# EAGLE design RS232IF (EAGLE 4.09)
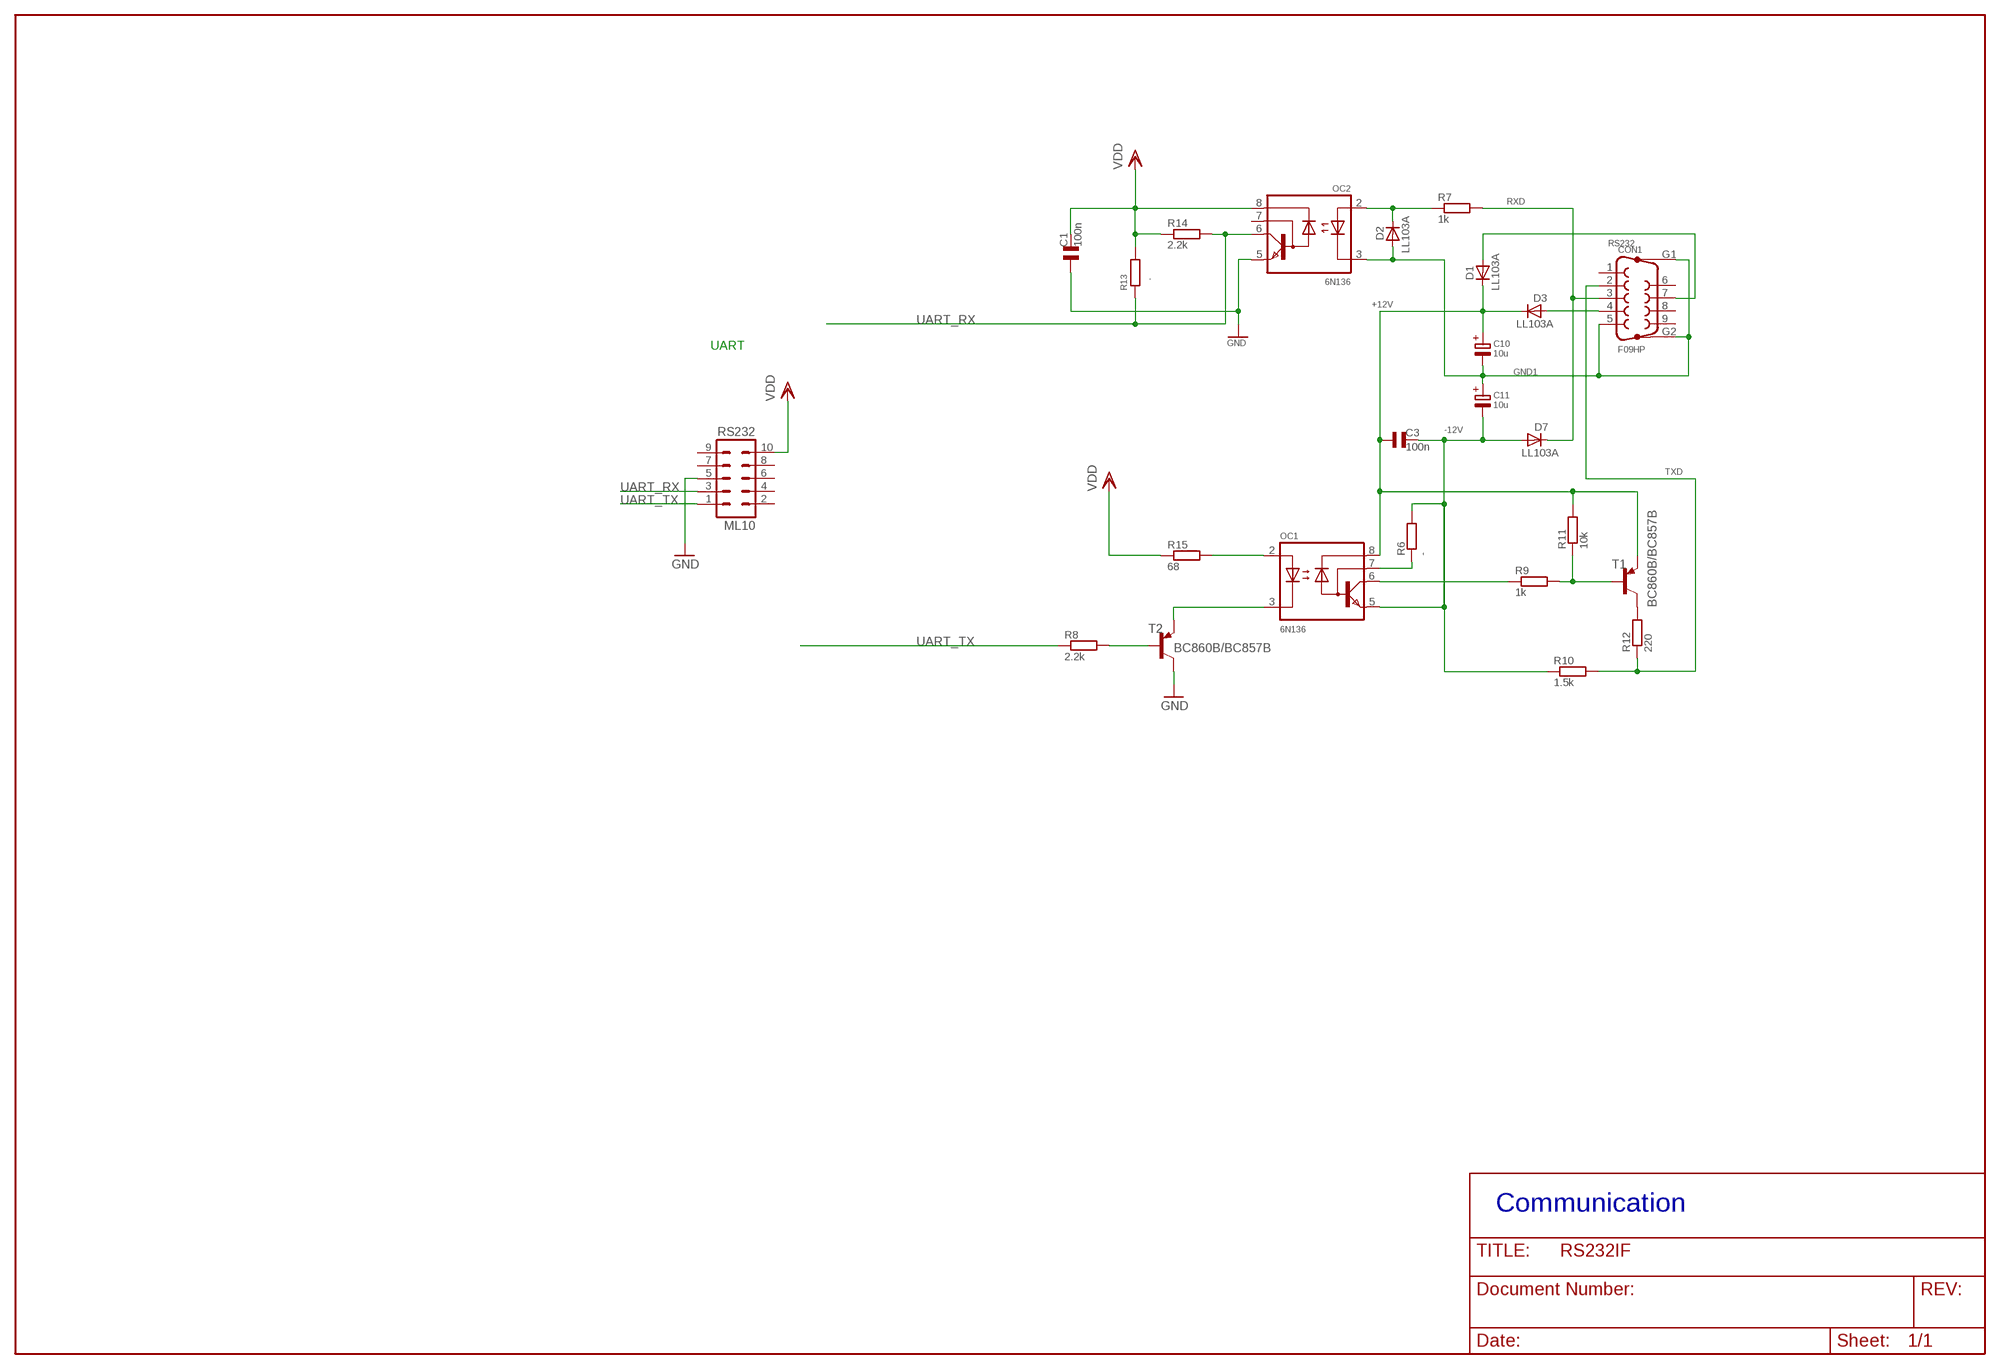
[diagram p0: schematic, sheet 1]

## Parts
C1  100n  CSMD0805  [CSMD0805]
C3  100n  CSMD0805  [CSMD0805]
C10  10u  ELKO  [7243]
C11  10u  ELKO  [7243]
CON1  F09HP  [F09HP]
D1  LL103A  D  [SOD-80]
D2  LL103A  D  [SOD-80]
D3  LL103A  D  [SOD-80]
D7  LL103A  D  [SOD-80]
OC1  6N136  6N135  [DIL08]
OC2  6N136  6N135  [DIL08]
R6  -  R_0805  [0805]
R7  1k  R_0805  [0805]
R8  2.2k  R_0805  [0805]
R9  1k  R_0805  [0805]
R10  1.5k  R_0805  [0805]
R11  10k  R_0805  [0805]
R12  220  R_0805  [0805]
R13  -  0204/5  [0805]
R14  2.2k  R_0805  [0805]
R15  68  R_0805  [0805]
RS232  ML10  [ML10]
T1  BC860B/BC857B  BC857ASMD  [SOT23-BEC]
T2  BC860B/BC857B  BC857ASMD  [SOT23-BEC]

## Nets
+12V: C3.1 C10.2 D1.2(K) D3.2(K) OC1.8(VCC) R11.2 T1.E
+12V1: CON1.4 D3.1(A)
+12V2: CON1.7 D1.1(A)
-12V: C3.2 C11.1 D7.1(A) OC1.5(GND) R6.2 R10.1
GND: C1.1 OC2.5(GND) RS232.5 T2.C
GND1: C10.1 C11.2 CON1.5 CON1.G1 CON1.G2 D2.1(A) OC2.3(K)
N$1: R8.2 T2.B
N$2: OC1.7(VB) R6.1
N$9: D2.2(K) OC2.2(A) R7.1
N$29: OC1.6(VO) R9.1
N$30: R9.2 R11.1 T1.B
N$32: R12.2 T1.C
N$49: OC1.2(A) R15.2
N$455: OC1.3(K) T2.E
RXD: CON1.3 D7.2(K) R7.2
TXD: CON1.2 R10.2 R12.1
UART_RX: OC2.6(VO) R13.1 R14.2 RS232.3
UART_TX: R8.1 RS232.1
VCC: C1.2 OC2.8(VCC) R13.2 R14.1 R15.1 RS232.10 ; supply symbol labelled VDD
Unconnected: CON1.1 CON1.6 CON1.8 CON1.9 OC2.7(VB) RS232.2 RS232.4 RS232.6 RS232.7 RS232.8 RS232.9

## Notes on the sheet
- RS232
- UART
- Communication

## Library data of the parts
C1 C3 = CAP:CSMD0805
C10 C11 = SMD-CAP:ELKO
CON1 = SUBD-A:F09HP
D1-D3 D7 = SMD:D
OC1 OC2 = OPTOCPL:6N135
R6-R12 R14 R15 = SMD:R_0805
R13 = R:0204/5
RS232 = con-ml:ML10
T1 T2 = transistor-pnp:BC857*: PNP Transistror

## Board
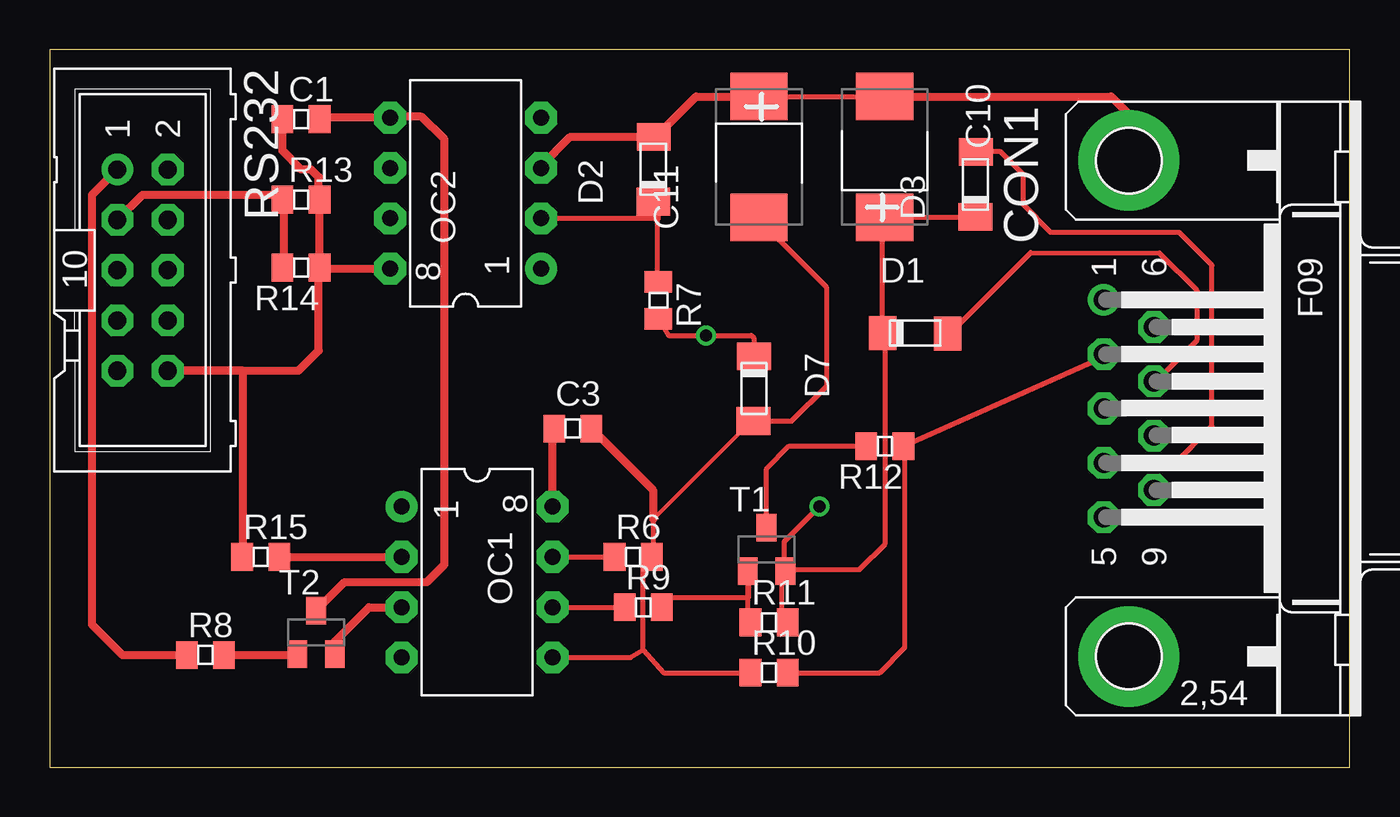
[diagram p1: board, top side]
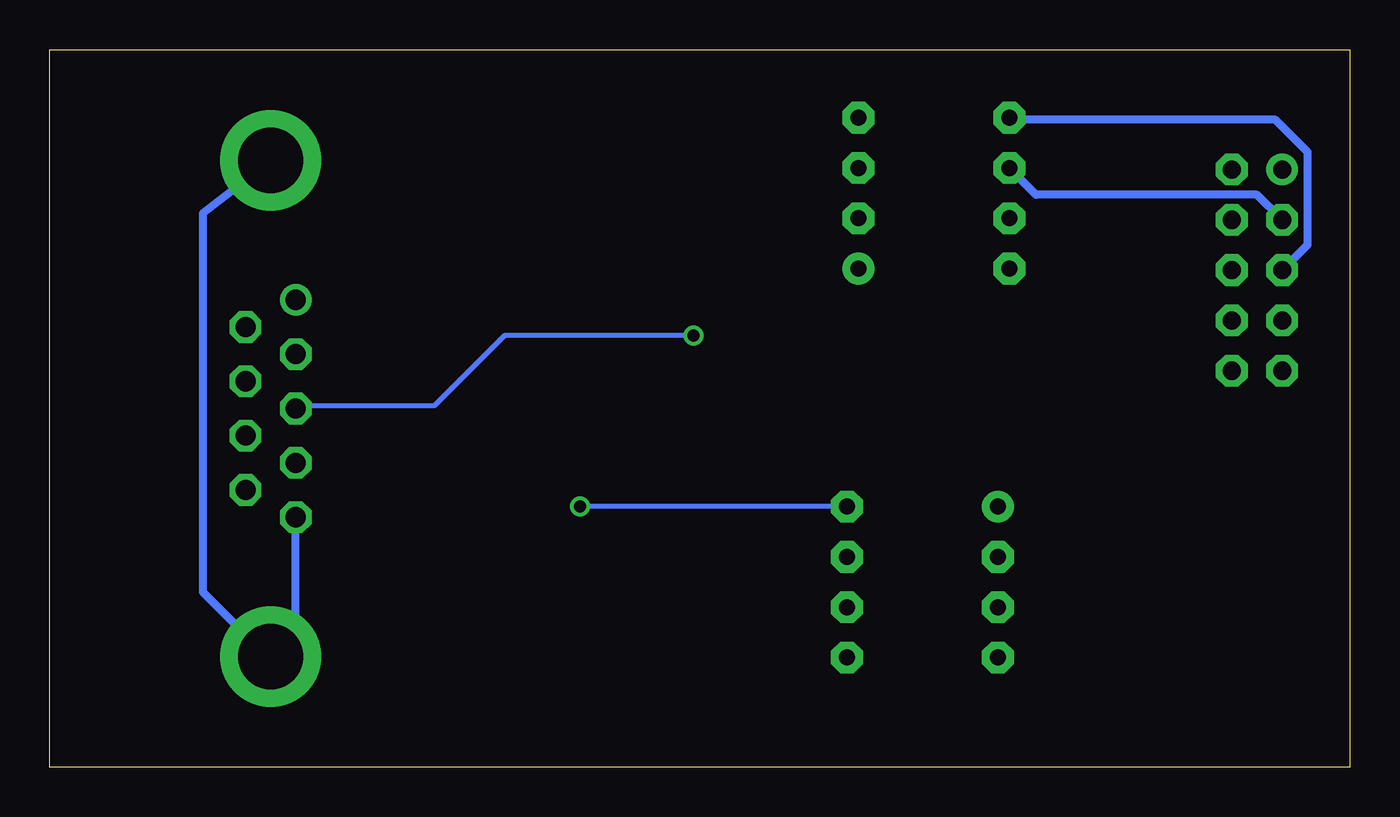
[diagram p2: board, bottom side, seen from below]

Size 65.64 x 36.25 mm. Coordinates in mm from the lower left corner, seen from the top.
Outline: 0,0 65.64,0 65.64,36.25 0,36.25 0,0
Copper layers (1*16): Top 0.035mm / dielectric 1.5mm / Bottom 0.035mm
Design rules "default": minimum track width 8mil, minimum drill 24mil, track to track 8mil, track to pad 8mil, pad to pad 6mil, via to via 8mil, smd to smd 8mil, copper to edge 40mil, drill to drill 8mil, minimum pad ring 10mil, minimum via ring 8mil, stop-mask expansion 4mil, vias tented up to drill 0mil, thermal gap 10mil

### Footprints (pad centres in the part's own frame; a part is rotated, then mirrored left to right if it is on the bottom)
CSMD0805 = smd 1.092 x 1.397: 1 -0.94,0; 2 0.94,0
7243 = smd 2.388 x 2.896: 1 -3.048,0; 2 3.048,0
F09HP = drill 1.016 pad 1.6 round: 1 -5.486,-1.27 | drill 1.016 pad 1.6 octagon: 2 -2.743,-1.27; 3 0,-1.27; 4 2.743,-1.27; 5 5.486,-1.27; 6 -4.115,1.27; 7 -1.372,1.27; 8 1.372,1.27; 9 4.115,1.27 | drill 3.302 pad 5.08 round: G1 -12.522,0; G2 12.522,0
SOD-80 = smd 1.397 x 1.702: 1 1.397,-0.025; 2 -1.88,0
DIL08 = drill 0.813 pad 1.6 round: 1 -3.81,-3.81 | drill 0.813 pad 1.6 octagon: 2 -1.27,-3.81; 3 1.27,-3.81; 4 3.81,-3.81; 5 3.81,3.81; 6 1.27,3.81; 7 -1.27,3.81; 8 -3.81,3.81
0805 = smd 1.092 x 1.397: 1 -0.94,0; 2 0.94,0
ML10 = drill 0.914 pad 1.6 round: 1 -5.08,-1.27 | drill 0.914 pad 1.6 octagon: 2 -5.08,1.27; 3 -2.54,-1.27; 4 -2.54,1.27; 5 0,-1.27; 6 0,1.27; 7 2.54,-1.27; 8 2.54,1.27; 9 5.08,-1.27; 10 5.08,1.27
SOT23-BEC = smd 1 x 1.4: B -0.95,-1.1; C 0,1.1; E 0.95,-1.1

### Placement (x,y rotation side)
C1  12.7,32.73 180 top
C3  26.41,17.11 0 top
C10  42.16,30.82 270 top
C11  35.81,30.82 90 top
CON1  54.48,18.12 270 top
D1  43.94,21.93 0 top
D2  30.47,30.44 90 top
D3  46.73,29.68 90 top
D7  35.55,18.89 270 top
OC1  21.58,9.36 270 top
OC2  21,28.99 90 top
R6  29.46,10.63 0 top
R7  30.73,23.58 270 top
R8  7.87,5.68 0 top
R9  29.97,8.09 0 top
R10  36.32,4.79 0 top
R11  36.32,7.33 0 top
R12  42.16,16.22 180 top
R13  12.7,28.66 0 top
R14  12.7,25.23 180 top
R15  10.66,10.63 0 top
RS232  4.69,25.11 270 top
T1  36.19,11.01 0 top
T2  13.46,6.82 0 top

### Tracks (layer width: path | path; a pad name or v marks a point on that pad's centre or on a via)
+12V  (via drill 0.61)
  Top 0.254: 42.03,21.81 42.03,21.55 42.06,21.55 42.06,21.78 | 42.03,21.81 42.03,27.65 C10.2 46.73,27.78 D3.2 | 36.99,9.91 36.95,9.87 36.95,7.71 37.33,7.33 R11.2 | 36.99,9.91 T1.E | 36.99,9.91 37.08,9.99 40.89,9.99 42.18,11.29 42.18,21.65 42.06,21.78 | 36.99,9.91 37.04,9.87 37.08,9.87 37.08,11.39 v38.86,13.17 | 42.06,21.78 42.03,21.81 | 42.03,21.81 D1.2
  Top 0.406: 25.39,13.04 OC1.8 25.39,17.03 C3.1
  Bottom 0.254: OC1.8 v38.86,13.17
+12V1
  Top 0.254: CON1.4 53.26,15.33 56.76,15.33 58.67,17.23 58.67,25.36 57.02,27.01 50.54,27.01 49.14,28.41 49.14,29.93 48,31.08 D3.1
+12V2
  Top 0.254: CON1.7 55.85,19.5 57.91,21.55 57.91,24.09 56.03,25.97 49.52,26 45.33,21.81 D1.1
-12V
  Top 0.203: 30.47,12.43 30.47,12.54 35.43,17.49
  Top 0.254: 30.47,12.43 30.47,10.5 30.6,10.5 30.47,10.63 | 29.97,5.93 29.33,5.55 OC1.5 | 29.97,5.93 29.97,10.12 30.47,10.63 | 30.47,10.63 R6.2 | 29.97,5.93 30.98,4.79 R10.1 | C11.1 35.81,27.65 39.24,24.22 39.24,19.27 37.46,17.49 35.55,17.49 | 35.55,17.49 D7.1 | 35.43,17.49 35.55,17.49
  Top 0.406: C3.2 30.47,13.98 30.47,12.54
GND
  Top 0.406: 13.63,32.65 13.58,32.6 | 13.63,32.65 C1.1 | 13.63,32.65 13.79,32.8 OC2.5 17.24,32.86 18.79,32.86 19.93,31.71 19.93,10.25 19.04,9.36 14.9,9.36 T2.C
  Bottom 0.406: RS232.5 2.15,26.38 2.15,31.08 3.8,32.73 17.27,32.73 OC2.5
GND1
  Top 0.254: 42.41,33.87 C10.1 C11.2 | D2.1 30.47,31.84 30.47,31.97 30.6,31.84
  Top 0.406: CON1.G1 54.48,32.98 53.59,33.87 C10.1 | C11.2 32.63,33.87 30.6,31.84 26.28,31.84 24.81,30.37 OC2.3
  Bottom 0.406: CON1.G1 57.91,27.98 57.91,8.85 54.48,5.42 54.48,5.55 | 54.48,5.55 CON1.G2 | CON1.5 53.21,6.82 54.48,5.55
N$1
  Top 0.406: 12.51,5.74 12.57,5.8 | 12.51,5.74 T2.B | R8.2 12.44,5.68 12.51,5.74
N$2
  Top 0.254: OC1.7 R6.1
N$9
  Top 0.254: OC2.2 30.65,27.72 30.65,24.55 30.73,24.35 R7.1
  Top 0.406: 30.65,27.72 30.6,28.31 30.35,28.31 D2.2
N$29
  Top 0.254: OC1.6 R9.1
N$30
  Top 0.254: R11.1 35.3,7.33 35.24,7.39 T1.B 35.24,9.87 35.3,9.87 35.3,8.6 30.91,8.6 R9.2
N$32
  Top 0.254: T1.C 36.19,15.07 37.33,16.22 R12.2
N$49
  Top 0.406: R15.2 11.6,10.68 11.68,10.76 11.81,10.63 OC1.2
N$455
  Top 0.406: T2.E 14.41,6.37 16.12,8.09 17.65,8.09 17.77,7.96 OC1.3
RXD  (via drill 0.61)
  Top 0.254: 33.27,21.81 35.43,21.81 35.55,21.68 D7.2 35.55,20.66 | 33.27,21.81 v33.14,21.81 | R7.2 31.24,21.81 33.27,21.81
  Bottom 0.254: v33.14,21.81 42.67,21.81 46.22,18.25 53.21,18.25 CON1.3
TXD
  Top 0.254: R10.2 41.91,4.79 43.17,6.06 43.17,16.22 R12.1 53.34,20.79 53.26,20.87 CON1.2
UART_RX
  Top 0.406: RS232.3 4.69,28.92 11.81,28.92 11.81,28.79 | 11.81,28.79 11.81,28.66 R13.1 | R14.2 11.81,25.23 11.81,28.79
  Bottom 0.406: OC2.6 15.85,28.92 4.69,28.92 RS232.3
UART_TX
  Top 0.406: RS232.1 2.15,28.92 2.15,7.2 3.68,5.68 R8.1
VCC
  Top 0.406: R15.1 9.77,10.63 9.77,20.03 RS232.10 12.57,20.03 13.58,21.04 13.58,25.11 13.71,25.23 R14.1 | R14.1 13.46,25.23 13.51,25.18 OC2.8 | R14.1 13.63,28.49 13.58,28.54 13.63,28.59 R13.2 13.58,28.66 13.58,29.81 13.2,30.19 12.7,30.19 11.76,31.13 C1.2

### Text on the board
tRestrict: MSP430 - RS232 IF | Rev.: 1.0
